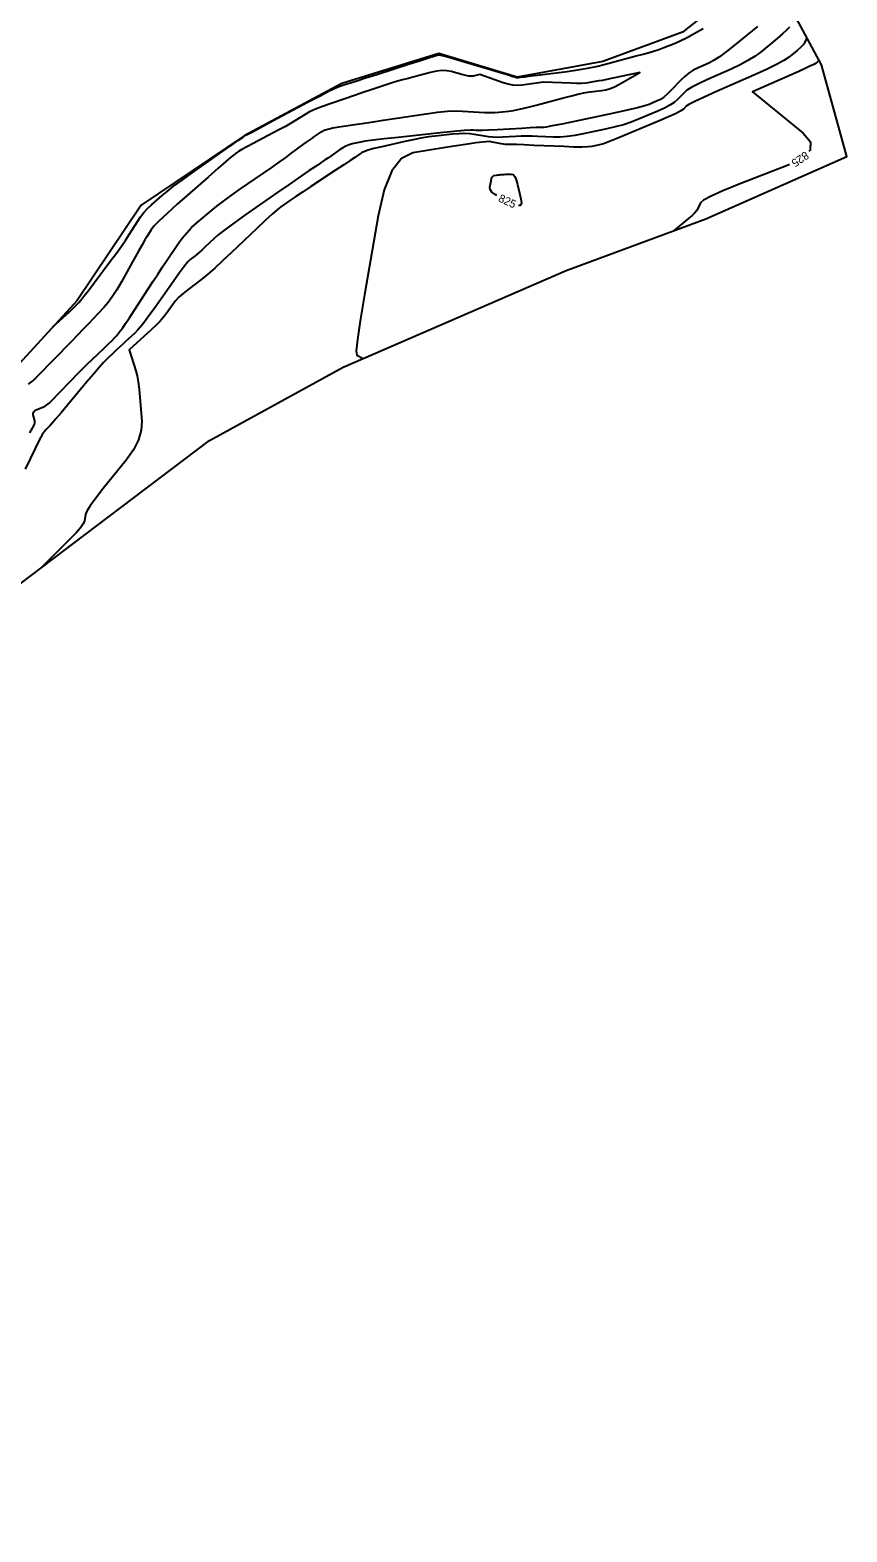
# Model space of a CAD drawing. Extents: x 1715724 to 1716561, y 394063 to 395906.
# Drawn here: x 1716206.5 to 1716349.4, y 394949.5 to 395212.3 of the extents above; entities that cross this region are included whole.
import ezdxf

# ---------------------------------------------------------------- set-up
doc = ezdxf.new("R2010")
doc.units = 0
for name, color, linetype in [('DT_X_Contour_Major', 7, 'Continuous'), ('DT_X_Contour_Minor', 7, 'Continuous'), ('DT_X_TIN_Hull', 7, 'Continuous')]:
    doc.layers.add(name, color=color, linetype=linetype)

msp = doc.modelspace()

# ---------------------------------------------------------------- linework, layer by layer
at = {"layer": 'DT_X_Contour_Major'}
for points in [[(1716344.49, 395207.09), (1716344.42, 395206.92), (1716344.39, 395206.88), (1716344.35, 395206.83), (1716344.27, 395206.76), (1716344.18, 395206.68), (1716343.9, 395206.45), (1716343.61, 395206.29), (1716342.93, 395205.97), (1716341.88, 395205.49), (1716340.45, 395204.85), (1716332.89, 395201.52), (1716341.76, 395194.26), (1716343.02, 395192.75), (1716343, 395191.31), (1716342.78, 395191.07)], [(1716288.18, 395183.34), (1716287.86, 395183.53), (1716287.32, 395183.97), (1716287.03, 395184.41), (1716286.98, 395184.83), (1716287.18, 395185.95), (1716287.26, 395186.33), (1716287.38, 395186.6), (1716287.51, 395186.77), (1716287.67, 395186.85), (1716288.14, 395186.93)], [(1716288.14, 395186.93), (1716288.44, 395186.98), (1716288.66, 395187), (1716288.89, 395187.03), (1716289.01, 395187.04), (1716289.19, 395187.05), (1716289.44, 395187.06), (1716289.76, 395187.08), (1716290.68, 395187.12), (1716291.02, 395187.01), (1716291.31, 395186.67), (1716291.58, 395186.1), (1716291.81, 395185.28), (1716292.39, 395182.8), (1716292.47, 395182.04), (1716292.26, 395181.63), (1716291.96, 395181.59)], [(1716339.35, 395188.76), (1716339.14, 395188.66), (1716330.57, 395185.33), (1716327.73, 395184.19), (1716325.66, 395183.27), (1716324.35, 395182.57), (1716323.79, 395182.09), (1716323.32, 395181.09), (1716323.1, 395180.7), (1716322.76, 395180.29), (1716322.33, 395179.85), (1716321.79, 395179.38), (1716319.02, 395177.15)]]:
    msp.add_lwpolyline(points, dxfattribs=at)
at = {"layer": 'DT_X_Contour_Minor'}
for points in [[(1716333.76, 395212.91), (1716329.75, 395209.64), (1716328.34, 395208.53), (1716327.12, 395207.64), (1716326.09, 395206.97), (1716325.24, 395206.53), (1716323.25, 395205.65), (1716322.51, 395205.28), (1716321.8, 395204.81), (1716321.1, 395204.25), (1716320.42, 395203.6), (1716318.64, 395201.74), (1716317.99, 395201.1), (1716317.37, 395200.58), (1716316.79, 395200.18), (1716316.24, 395199.9), (1716314.84, 395199.31), (1716314.05, 395199.04), (1716312.76, 395198.7), (1716310.96, 395198.28), (1716308.64, 395197.78), (1716301.79, 395196.34), (1716299.53, 395195.87), (1716297.88, 395195.53), (1716296.83, 395195.33), (1716296.4, 395195.27), (1716296.06, 395195.29), (1716295.74, 395195.28), (1716295.05, 395195.25), (1716293.99, 395195.19), (1716292.55, 395195.1), (1716288.23, 395194.85), (1716286.79, 395194.77), (1716285.7, 395194.72), (1716284.98, 395194.71), (1716284.61, 395194.72), (1716284.11, 395194.82), (1716283.61, 395194.82), (1716282.46, 395194.73), (1716280.67, 395194.56), (1716278.24, 395194.31), (1716270.92, 395193.54), (1716268.45, 395193.27), (1716266.53, 395193.04), (1716265.16, 395192.86), (1716264.34, 395192.71), (1716262.88, 395192.38), (1716262.34, 395192.22), (1716261.79, 395191.99), (1716261.23, 395191.7), (1716260.67, 395191.34), (1716259.18, 395190.3), (1716258.62, 395189.91), (1716258.05, 395189.52), (1716257.48, 395189.13), (1716256.9, 395188.75), (1716255.36, 395187.73), (1716254.58, 395187.21), (1716253.41, 395186.4), (1716251.84, 395185.31), (1716249.88, 395183.94), (1716244.12, 395179.91), (1716242.16, 395178.52), (1716240.6, 395177.37), (1716239.44, 395176.47), (1716238.67, 395175.81), (1716237.16, 395174.36), (1716236.63, 395173.86), (1716236.15, 395173.43), (1716235.74, 395173.08), (1716235.4, 395172.8), (1716234.56, 395172.16), (1716234.14, 395171.74), (1716233.49, 395170.95), (1716232.63, 395169.79), (1716231.54, 395168.26), (1716228.34, 395163.7), (1716227.22, 395162.14), (1716226.26, 395160.88), (1716225.46, 395159.92), (1716224.81, 395159.25), (1716223.3, 395157.88), (1716222.74, 395157.37), (1716222.21, 395156.88), (1716221.71, 395156.4), (1716221.23, 395155.94), (1716219.97, 395154.72), (1716219.4, 395154.13), (1716218.63, 395153.27), (1716217.66, 395152.15), (1716216.49, 395150.76), (1716213.1, 395146.71), (1716211.96, 395145.35), (1716211.06, 395144.29), (1716210.42, 395143.54), (1716210.03, 395143.11), (1716209.31, 395142.35), (1716209.07, 395142.08), (1716208.87, 395141.84), (1716208.71, 395141.63), (1716208.61, 395141.46), (1716208.39, 395141.03), (1716208.27, 395140.79), (1716208.07, 395140.39), (1716207.8, 395139.84), (1716207.45, 395139.13), (1716205.65, 395135.46)], [(1716339.35, 395212.81), (1716338.87, 395212.27), (1716338.16, 395211.62), (1716337.23, 395210.83), (1716334.46, 395208.58), (1716333.36, 395207.75), (1716332.11, 395206.96), (1716330.72, 395206.2), (1716329.19, 395205.47), (1716324.92, 395203.59), (1716323.47, 395202.92), (1716322.31, 395202.31), (1716321.44, 395201.77), (1716320.87, 395201.29), (1716319.72, 395200.1), (1716319.19, 395199.64), (1716318.45, 395199.16), (1716317.5, 395198.66), (1716316.34, 395198.14), (1716312.98, 395196.72), (1716311.69, 395196.21), (1716310.32, 395195.75), (1716308.89, 395195.35), (1716307.39, 395195), (1716303.29, 395194.14), (1716301.82, 395193.86), (1716300.47, 395193.68), (1716299.24, 395193.59), (1716298.14, 395193.59), (1716295.36, 395193.71), (1716294.34, 395193.75), (1716293.36, 395193.76), (1716292.42, 395193.74), (1716291.52, 395193.7), (1716289.17, 395193.56), (1716288.31, 395193.53), (1716287.5, 395193.55), (1716286.74, 395193.61), (1716286.03, 395193.72), (1716284.2, 395194.06), (1716283.46, 395194.16), (1716282.59, 395194.2), (1716281.61, 395194.17), (1716280.5, 395194.08), (1716277.4, 395193.75), (1716276.2, 395193.6), (1716274.9, 395193.4), (1716273.52, 395193.13), (1716272.06, 395192.81), (1716268.04, 395191.89), (1716266.69, 395191.56), (1716265.65, 395191.27), (1716264.91, 395191.02), (1716264.49, 395190.82), (1716263.77, 395190.31), (1716263.33, 395190.01), (1716262.55, 395189.49), (1716261.43, 395188.75), (1716259.98, 395187.79), (1716255.66, 395184.94), (1716254.19, 395183.97), (1716253.02, 395183.18), (1716252.14, 395182.59), (1716251.56, 395182.2), (1716250.4, 395181.39), (1716249.82, 395180.93), (1716248.93, 395180.14), (1716247.73, 395179.04), (1716246.22, 395177.61), (1716241.79, 395173.38), (1716240.22, 395171.91), (1716238.84, 395170.65), (1716237.64, 395169.62), (1716236.63, 395168.81), (1716234.17, 395166.93), (1716233.32, 395166.24), (1716232.58, 395165.57), (1716231.97, 395164.93), (1716231.48, 395164.3), (1716230.34, 395162.68), (1716229.86, 395162.05), (1716229.27, 395161.38), (1716228.58, 395160.67), (1716227.79, 395159.92), (1716223.85, 395156.34), (1716225.01, 395152.69), (1716225.24, 395151.81), (1716225.44, 395150.74), (1716225.61, 395149.48), (1716225.75, 395148.02), (1716226.07, 395143.89), (1716225.99, 395142.3), (1716225.51, 395140.64), (1716224.62, 395138.89), (1716223.32, 395137.06), (1716219.33, 395132.09), (1716218.02, 395130.41), (1716217.06, 395129.08), (1716216.45, 395128.12), (1716216.21, 395127.53), (1716216.03, 395126.42), (1716215.83, 395125.92), (1716215.38, 395125.24), (1716214.66, 395124.4), (1716213.69, 395123.39), (1716208.55, 395118.27)], [(1716210.48, 395160.33), (1716212.9, 395162.52), (1716213.38, 395162.96), (1716213.79, 395163.35), (1716214.14, 395163.69), (1716214.41, 395163.98), (1716215.05, 395164.66), (1716215.4, 395165.07), (1716215.96, 395165.77), (1716216.73, 395166.77), (1716217.72, 395168.07), (1716220.63, 395171.92), (1716221.66, 395173.3), (1716222.54, 395174.52), (1716223.28, 395175.59), (1716223.89, 395176.52), (1716225.31, 395178.8), (1716225.86, 395179.62), (1716226.46, 395180.39), (1716227.1, 395181.09), (1716227.77, 395181.73), (1716229.64, 395183.37), (1716230.49, 395184.08), (1716231.65, 395184.98), (1716233.13, 395186.06), (1716234.91, 395187.33), (1716240.07, 395190.98), (1716241.78, 395192.18), (1716243.01, 395193.05), (1716243.78, 395193.59), (1716244.09, 395193.8), (1716244.28, 395193.91), (1716244.63, 395194.1), (1716245.54, 395194.59), (1716249.03, 395196.46), (1716255.18, 395199.74), (1716257.26, 395200.83), (1716258.87, 395201.66), (1716260.02, 395202.21), (1716260.71, 395202.49), (1716261.94, 395202.88), (1716262.61, 395203.09), (1716263.71, 395203.44), (1716265.23, 395203.93), (1716267.18, 395204.55), (1716272.93, 395206.38), (1716274.84, 395206.99), (1716276.24, 395207.43), (1716277.14, 395207.72), (1716277.54, 395207.84), (1716277.94, 395207.95), (1716278.31, 395207.92), (1716279.13, 395207.72), (1716280.39, 395207.38), (1716282.11, 395206.88), (1716287.27, 395205.33), (1716288.98, 395204.82), (1716290.22, 395204.45), (1716291, 395204.21), (1716291.31, 395204.11), (1716291.52, 395204.04), (1716291.6, 395204.01), (1716291.68, 395204), (1716291.75, 395203.99), (1716291.83, 395204), (1716292.02, 395204.03), (1716292.31, 395204.06), (1716293.02, 395204.15), (1716294.16, 395204.29), (1716295.73, 395204.49), (1716300.49, 395205.08), (1716302.27, 395205.33), (1716304.05, 395205.65), (1716305.83, 395206.02), (1716307.6, 395206.46), (1716312.34, 395207.72), (1716313.99, 395208.16), (1716315.38, 395208.57), (1716316.51, 395208.93), (1716317.39, 395209.24), (1716319.38, 395210.03), (1716320.25, 395210.41), (1716321.35, 395210.97), (1716322.68, 395211.7), (1716324.25, 395212.61)], [(1716342.42, 395210.96), (1716342.02, 395210.07), (1716341.87, 395209.84), (1716341.61, 395209.55), (1716341.22, 395209.19), (1716340.71, 395208.76), (1716339.18, 395207.51), (1716338.38, 395206.97), (1716337.1, 395206.28), (1716335.35, 395205.42), (1716333.13, 395204.42), (1716326.6, 395201.54), (1716324.43, 395200.56), (1716322.82, 395199.81), (1716321.79, 395199.29), (1716321.31, 395198.98), (1716320.81, 395198.45), (1716320.39, 395198.17), (1716319.53, 395197.73), (1716318.21, 395197.13), (1716316.44, 395196.37), (1716311.13, 395194.13), (1716309.32, 395193.37), (1716307.89, 395192.81), (1716306.82, 395192.43), (1716306.13, 395192.23), (1716304.79, 395191.94), (1716304.1, 395191.86), (1716303.05, 395191.83), (1716301.65, 395191.84), (1716299.88, 395191.91), (1716294.67, 395192.14), (1716292.95, 395192.21), (1716291.68, 395192.27), (1716290.86, 395192.29), (1716290.49, 395192.3), (1716290.11, 395192.27), (1716289.93, 395192.28), (1716289.67, 395192.3), (1716289.34, 395192.35), (1716288.93, 395192.43), (1716286.86, 395192.82), (1716284.5, 395192.57), (1716283.79, 395192.48), (1716282.67, 395192.31), (1716281.14, 395192.07), (1716279.2, 395191.76), (1716273.49, 395190.82), (1716271.5, 395189.86), (1716269.82, 395187.7), (1716268.46, 395184.34), (1716267.4, 395179.78), (1716265.01, 395165.99), (1716264.25, 395161.45), (1716263.78, 395158.18), (1716263.59, 395156.16), (1716263.68, 395155.41), (1716264.78, 395154.85)], [(1716206.49, 395141.87), (1716207.17, 395143.07), (1716207.29, 395143.34), (1716207.35, 395143.61), (1716207.36, 395143.89), (1716207.3, 395144.19), (1716207.09, 395144.99), (1716207.07, 395145.27), (1716207.17, 395145.52), (1716207.39, 395145.73), (1716207.72, 395145.91), (1716208.79, 395146.33), (1716209.25, 395146.59), (1716209.85, 395147.06), (1716210.57, 395147.72), (1716211.42, 395148.59), (1716213.87, 395151.17), (1716214.77, 395152.11), (1716215.65, 395153), (1716216.5, 395153.84), (1716217.32, 395154.62), (1716219.47, 395156.64), (1716220.21, 395157.35), (1716220.82, 395157.95), (1716221.3, 395158.45), (1716221.64, 395158.84), (1716222.38, 395159.74), (1716222.74, 395160.22), (1716223.25, 395160.96), (1716223.93, 395161.97), (1716224.76, 395163.25), (1716227.19, 395167.02), (1716228.08, 395168.39), (1716228.92, 395169.67), (1716229.72, 395170.87), (1716230.46, 395171.99), (1716232.39, 395174.85), (1716233.14, 395175.89), (1716233.94, 395176.85), (1716234.8, 395177.75), (1716235.71, 395178.57), (1716238.21, 395180.67), (1716239.22, 395181.49), (1716240.39, 395182.39), (1716241.71, 395183.35), (1716243.19, 395184.39), (1716247.34, 395187.26), (1716248.8, 395188.28), (1716250.09, 395189.18), (1716251.19, 395189.96), (1716252.11, 395190.63), (1716254.33, 395192.26), (1716255.09, 395192.82), (1716255.74, 395193.29), (1716256.26, 395193.66), (1716256.65, 395193.94), (1716257.54, 395194.55), (1716257.97, 395194.77), (1716258.63, 395194.98), (1716259.49, 395195.18), (1716260.57, 395195.36), (1716263.72, 395195.84), (1716265.02, 395196.04), (1716266.54, 395196.27), (1716268.29, 395196.53), (1716270.27, 395196.82), (1716275.84, 395197.66), (1716277.81, 395197.92), (1716279.52, 395198.09), (1716280.98, 395198.16), (1716282.18, 395198.14), (1716285.06, 395197.94), (1716286.09, 395197.89), (1716287.01, 395197.87), (1716287.83, 395197.89), (1716288.53, 395197.94), (1716290.28, 395198.13), (1716291.07, 395198.24), (1716292.12, 395198.46), (1716293.44, 395198.77), (1716295.03, 395199.19), (1716299.62, 395200.41), (1716301.22, 395200.83), (1716302.57, 395201.15), (1716303.67, 395201.37), (1716304.53, 395201.5), (1716306.49, 395201.72), (1716307.23, 395201.85), (1716307.98, 395202.07), (1716308.75, 395202.39), (1716309.53, 395202.79), (1716313.19, 395204.91), (1716309.03, 395204), (1716308.18, 395203.81), (1716307.39, 395203.65), (1716306.68, 395203.51), (1716306.03, 395203.4), (1716304.41, 395203.12), (1716303.75, 395203.03), (1716302.98, 395202.98), (1716302.11, 395202.97), (1716301.14, 395202.99), (1716296.35, 395203.18), (1716292.62, 395202.67), (1716291.81, 395202.61), (1716290.99, 395202.66), (1716290.14, 395202.82), (1716289.28, 395203.08), (1716285.2, 395204.54), (1716284.01, 395204.26), (1716283.7, 395204.23), (1716283.27, 395204.27), (1716282.74, 395204.37), (1716282.08, 395204.53), (1716280.19, 395205.06), (1716279.44, 395205.2), (1716278.59, 395205.22), (1716277.64, 395205.12), (1716276.6, 395204.89), (1716273.7, 395204.14), (1716272.66, 395203.86), (1716271.7, 395203.6), (1716270.83, 395203.35), (1716270.06, 395203.11), (1716268.1, 395202.48), (1716267.26, 395202.21), (1716266.2, 395201.86), (1716264.93, 395201.43), (1716263.44, 395200.92), (1716259.19, 395199.48), (1716257.71, 395198.95), (1716256.46, 395198.45), (1716255.44, 395197.99), (1716254.65, 395197.55), (1716252.84, 395196.43), (1716252.09, 395195.97), (1716251.19, 395195.46), (1716250.14, 395194.89), (1716248.95, 395194.26), (1716245.57, 395192.49), (1716244.44, 395191.89), (1716243.57, 395191.41), (1716242.97, 395191.07), (1716242.63, 395190.85), (1716242.09, 395190.44), (1716241.66, 395190.08), (1716240.78, 395189.32), (1716239.44, 395188.15), (1716237.66, 395186.58), (1716232.29, 395181.83), (1716230.5, 395180.22), (1716229.13, 395178.94), (1716228.2, 395177.99), (1716227.71, 395177.37), (1716226.95, 395176.16), (1716226.6, 395175.58), (1716226.12, 395174.73), (1716225.49, 395173.63), (1716224.73, 395172.26), (1716222.52, 395168.27), (1716221.71, 395166.87), (1716220.92, 395165.65), (1716220.17, 395164.62), (1716219.45, 395163.78), (1716217.57, 395161.78), (1716216.79, 395160.96), (1716215.88, 395160.01), (1716214.83, 395158.92), (1716213.65, 395157.7), (1716207.79, 395151.69), (1716207.51, 395151.39), (1716207.46, 395151.33), (1716207.41, 395151.28), (1716207.36, 395151.23), (1716207.32, 395151.19), (1716207.21, 395151.09), (1716207.07, 395150.99), (1716206.73, 395150.75), (1716206.2, 395150.37)]]:
    msp.add_lwpolyline(points, dxfattribs=at)
at = {"layer": 'DT_X_TIN_Hull'}
for points in [[(1716335.25, 395223.51), (1716320.65, 395211.92), (1716306.73, 395206.83), (1716291.71, 395204.04), (1716278.01, 395208.19), (1716261.04, 395202.98), (1716243.98, 395193.78), (1716225.98, 395181.67), (1716214.77, 395165.02), (1716203.32, 395152.5), (1716198.08, 395146.2), (1716187.29, 395139.29), (1716176.97, 395127.47), (1716165.6, 395115.64), (1716155.48, 395107.53), (1716139.02, 395097.43), (1716122.72, 395086.97), (1716119.12, 395087.96), (1716105.99, 395083.1), (1716092.42, 395101.27), (1716090.34, 395107.35), (1716087.9, 395121.25), (1716081.11, 395137.01), (1716069.7, 395157.33)], [(1716173.81, 394948.17), (1716164.24, 394964.1), (1716158.6, 394970.07), (1716161.28, 395011.43), (1716153.51, 395030.9), (1716140.07, 395054.98), (1716157.64, 395075.49), (1716176.81, 395091.39), (1716197.29, 395109.75), (1716218.02, 395125.43), (1716237.91, 395140.5), (1716261.28, 395153.34), (1716300.31, 395170.24), (1716324.76, 395179.27), (1716349.42, 395190.19), (1716344.96, 395206.21), (1716337.66, 395219.83)]]:
    msp.add_lwpolyline(points, dxfattribs=at)

# ---------------------------------------------------------------- texts
at = {"layer": 'DT_X_Contour_Major'}
for rotation, p in [(213.9038, (1716342.15, 395191.17)), (335.2159, (1716288.31, 395182.39))]:
    msp.add_text('825', height=1.4, rotation=rotation, dxfattribs=at).set_placement(p)

doc.saveas('drawing.dxf')
